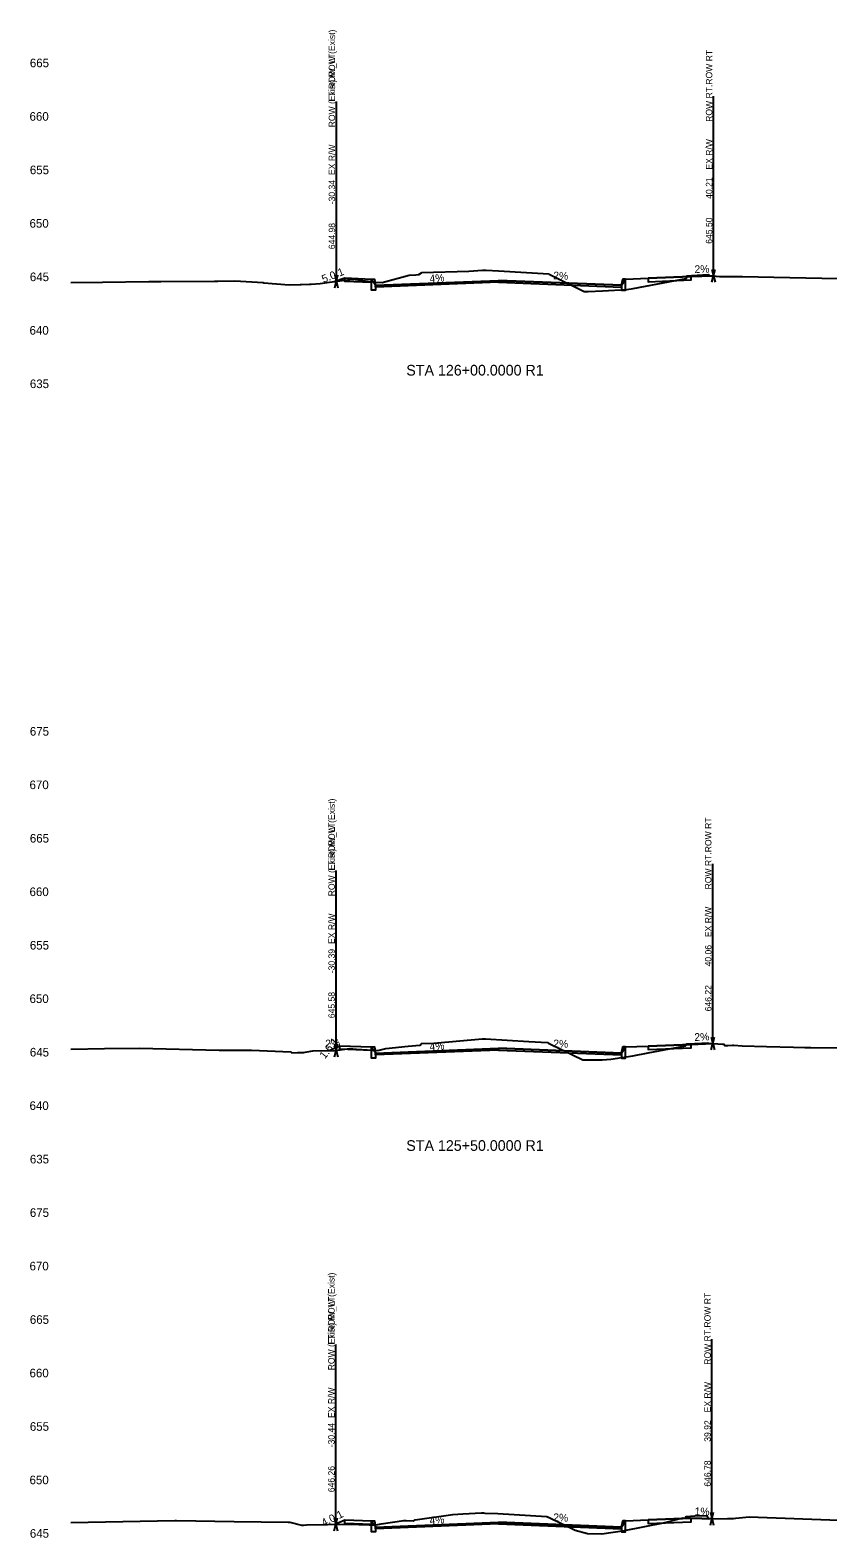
# Model space of a CAD drawing. Extents: x 2 to 741, y 16 to 2207.
# Drawn here: x 2.4 to 151.6, y 1390 to 1671.9 of the extents above; entities that cross this region are included whole.
import ezdxf

# ---------------------------------------------------------------- set-up
doc = ezdxf.new("R2010")
doc.units = 0
for name, color, linetype in [('Draft_XS_Feature_Name', 7, 'Continuous'), ('Draft_XS_Label', 7, 'Continuous'), ('Draft_XS_Point_Label_Indicator', 7, 'Continuous'), ('Draft_XS_Terminator', 7, 'Continuous'), ('Draft_XS_Text', 7, 'Continuous'), ('E_ROW', 7, 'Continuous'), ('E_Terrain_Exterior', 7, 'Continuous'), ('E_Terrain_Points_Low', 7, 'Continuous'), ('Grade_Veg_Grass', 7, 'Continuous'), ('P_XS_Sections', 7, 'Continuous'), ('Road_Curb', 7, 'Continuous'), ('Road_Pave_Asphalt', 7, 'Continuous'), ('Road_Sidewalk', 7, 'Continuous'), ('Terrain_Design', 7, 'Continuous')]:
    doc.layers.add(name, color=color, linetype=linetype)

msp = doc.modelspace()

# ---------------------------------------------------------------- linework, layer by layer
at = {"layer": 'Draft_XS_Terminator'}
for p, q in [((59.66, 1624.97), (59.66, 1646.97)), ((59.66, 1624.97), (59.66, 1646.97)), ((130.21, 1625.99), (130.21, 1647.99)), ((59.61, 1481.16), (59.61, 1503.16)), ((59.61, 1481.16), (59.61, 1503.16)), ((130.06, 1482.44), (130.06, 1504.44)), ((129.92, 1393.55), (129.92, 1415.55)), ((59.56, 1392.51), (59.56, 1414.51)), ((59.56, 1392.51), (59.56, 1414.51))]:
    msp.add_line(p, q, dxfattribs=at)
at = {"layer": 'E_ROW'}
for p, q in [((59.66, 1624.97), (59.66, 1658.57)), ((59.66, 1624.97), (59.66, 1658.57)), ((130.21, 1625.99), (130.21, 1659.59)), ((129.91, 1624.79), (130.51, 1627.19)), ((129.91, 1627.19), (130.51, 1624.79)), ((59.36, 1623.77), (59.96, 1626.17)), ((59.36, 1626.17), (59.96, 1623.77)), ((59.36, 1623.77), (59.96, 1626.17)), ((59.36, 1626.17), (59.96, 1623.77)), ((59.61, 1481.16), (59.61, 1514.76)), ((59.61, 1481.16), (59.61, 1514.76)), ((130.06, 1482.44), (130.06, 1516.04)), ((129.76, 1481.24), (130.36, 1483.64)), ((129.76, 1483.64), (130.36, 1481.24)), ((59.31, 1479.96), (59.91, 1482.36)), ((59.31, 1482.36), (59.91, 1479.96)), ((59.31, 1479.96), (59.91, 1482.36)), ((59.31, 1482.36), (59.91, 1479.96)), ((129.92, 1393.55), (129.92, 1427.15)), ((59.56, 1392.51), (59.56, 1426.11)), ((59.56, 1392.51), (59.56, 1426.11)), ((59.26, 1391.31), (59.86, 1393.71)), ((59.26, 1393.71), (59.86, 1391.31)), ((59.26, 1391.31), (59.86, 1393.71)), ((59.26, 1393.71), (59.86, 1391.31)), ((129.62, 1392.35), (130.22, 1394.75)), ((129.62, 1394.75), (130.22, 1392.35))]:
    msp.add_line(p, q, dxfattribs=at)
at = {"layer": 'E_Terrain_Exterior'}
for points in [[(10, 1624.72), (15.93, 1624.83), (24.58, 1624.94), (26.83, 1624.95), (36.85, 1624.99), (37.49, 1625), (40.69, 1625.04), (45.95, 1624.72), (46.06, 1624.71), (50.84, 1624.32), (52.86, 1624.39), (52.94, 1624.39), (52.99, 1624.39), (53.09, 1624.4), (54.61, 1624.45), (54.94, 1624.46), (56.62, 1624.55), (58.38, 1624.78), (62.66, 1625.4), (67.06, 1624.84), (68.2, 1624.77), (73.3, 1626.09), (74.49, 1626.2), (75.11, 1626.26), (75.57, 1626.56), (75.63, 1626.63), (84.44, 1626.84), (87.02, 1627.08), (87.14, 1627.07), (87.7, 1627.06), (90.01, 1626.92), (99.38, 1626.34), (99.44, 1626.3), (100.72, 1625.7), (106.01, 1623.04), (106.75, 1623.04), (109.47, 1623.16), (113.97, 1623.45), (115.15, 1623.62), (123.08, 1625.13), (125.08, 1625.52), (125.13, 1625.57), (125.29, 1625.99), (126.1, 1626.03), (129.27, 1626.24), (129.48, 1626.05), (131.35, 1625.9), (131.46, 1625.9), (131.87, 1625.89), (132.04, 1625.89), (132.23, 1625.88), (133.08, 1625.87), (134.11, 1625.85), (135.61, 1625.88), (141.49, 1625.77), (153.47, 1625.52)], [(10, 1481.37), (16.27, 1481.48), (22.83, 1481.53), (37.76, 1481.21), (43.76, 1481.16), (51.15, 1480.85), (51.3, 1480.69), (52.41, 1480.73), (52.48, 1480.73), (52.55, 1480.73), (53.29, 1480.76), (53.51, 1480.77), (53.56, 1480.77), (53.82, 1480.78), (55.26, 1481.04), (59.48, 1481.14), (62.09, 1481.52), (63.41, 1481.35), (67.4, 1481.11), (68.93, 1481.5), (73.11, 1481.91), (75.28, 1482.13), (75.4, 1482.2), (75.61, 1482.44), (77.88, 1482.49), (86.92, 1483.33), (87.35, 1483.31), (87.57, 1483.31), (95.65, 1482.81), (99.12, 1482.6), (99.34, 1482.48), (103.85, 1480.33), (105.78, 1479.36), (108.39, 1479.35), (109.38, 1479.39), (111.02, 1479.5), (115.1, 1480.11), (118, 1480.66), (124.96, 1482.02), (125.13, 1482.19), (125.19, 1482.34), (128, 1482.5), (129.16, 1482.58), (129.23, 1482.51), (131.94, 1482.28), (132.13, 1482.32), (132.24, 1482.07), (132.45, 1482.08), (132.62, 1482.08), (132.81, 1482.08), (132.87, 1482.08), (133.74, 1482.09), (134.01, 1482.1), (135.58, 1482.02), (140.12, 1481.86), (145.17, 1481.76), (147.28, 1481.71), (148.4, 1481.69), (166.65, 1481.64)], [(10, 1392.85), (29.45, 1393.2), (29.74, 1393.21), (40.54, 1393.06), (50.67, 1392.92), (50.85, 1392.92), (50.85, 1392.91), (50.93, 1392.89), (53.14, 1392.34), (53.5, 1392.36), (54.06, 1392.39), (61.9, 1392.56), (65.79, 1392.38), (67.07, 1392.43), (68.06, 1392.57), (72.29, 1393.2), (72.74, 1393.23), (74.11, 1393.14), (74.14, 1393.16), (74.42, 1393.33), (81.43, 1394.34), (83.29, 1394.47), (86.82, 1394.64), (87.02, 1394.64), (87.15, 1394.63), (87.45, 1394.62), (89.83, 1394.52), (99.01, 1393.96), (99.25, 1393.82), (99.32, 1393.82), (104.35, 1391.43), (106.63, 1390.76), (109.34, 1390.75), (113.58, 1391.38), (120.82, 1392.79), (124.53, 1393.71), (124.9, 1393.66), (125.05, 1393.8), (125.11, 1393.99), (127.54, 1394.14), (128.97, 1394.1), (129.18, 1393.6), (129.22, 1393.55), (132.82, 1393.59), (132.88, 1393.59), (132.96, 1393.59), (133.38, 1393.59), (133.91, 1393.59), (133.94, 1393.59), (134.38, 1393.68), (136.86, 1393.88), (155.31, 1393.21)]]:
    msp.add_lwpolyline(points, dxfattribs=at)
at = {"layer": 'Grade_Veg_Grass'}
for points in [[(59.25, 1624.91), (59.25, 1624.91), (61.25, 1625.6)], [(113.75, 1625.4), (118, 1625.57)], [(130, 1626.01), (126, 1625.89), (126, 1625.89)], [(58.28, 1481.11), (58.28, 1481.11), (60.28, 1482.02)], [(113.75, 1481.78), (118, 1481.95)], [(130, 1482.45), (126, 1482.27), (126, 1482.27)], [(59.25, 1392.5), (59.25, 1392.5), (61.25, 1393.36)], [(113.75, 1393.16), (118, 1393.33)], [(130, 1393.55), (130, 1393.55), (126, 1393.65)]]:
    msp.add_lwpolyline(points, dxfattribs=at)
at = {"layer": 'Road_Curb'}
for points in [[(67, 1624.23), (67, 1623.32), (66.25, 1623.32), (66.25, 1625.4), (66.77, 1625.4), (67, 1624.23)], [(113, 1624.23), (113, 1623.32), (113.75, 1623.32), (113.75, 1625.4), (113.23, 1625.4), (113, 1624.23)], [(67, 1480.61), (67, 1479.7), (66.25, 1479.7), (66.25, 1481.78), (66.77, 1481.78), (67, 1480.61)], [(113, 1480.61), (113, 1479.7), (113.75, 1479.7), (113.75, 1481.78), (113.23, 1481.78), (113, 1480.61)], [(67, 1391.99), (67, 1391.08), (66.25, 1391.08), (66.25, 1393.16), (66.77, 1393.16), (67, 1391.99)], [(113, 1391.99), (113, 1391.08), (113.75, 1391.08), (113.75, 1393.16), (113.23, 1393.16), (113, 1391.99)]]:
    msp.add_lwpolyline(points, dxfattribs=at)
at = {"layer": 'Road_Pave_Asphalt'}
for points in [[(90, 1625.15), (90, 1624.82), (67, 1623.9), (67, 1624.23), (90, 1625.15)], [(90, 1625.15), (90, 1624.82), (113, 1623.9), (113, 1624.23), (90, 1625.15)], [(90, 1481.53), (90, 1481.2), (67, 1480.28), (67, 1480.61), (90, 1481.53)], [(90, 1481.53), (90, 1481.2), (113, 1480.28), (113, 1480.61), (90, 1481.53)], [(90, 1392.91), (90, 1392.58), (67, 1391.66), (67, 1391.99), (90, 1392.91)], [(90, 1392.91), (90, 1392.58), (113, 1391.66), (113, 1391.99), (90, 1392.91)]]:
    msp.add_lwpolyline(points, dxfattribs=at)
at = {"layer": 'Road_Sidewalk'}
for points in [[(66.25, 1625.4), (66.25, 1624.73), (61.25, 1624.93), (61.25, 1625.6), (66.25, 1625.4)], [(118, 1625.57), (118, 1624.9), (126, 1625.22), (126, 1625.89), (118, 1625.57)], [(66.25, 1481.78), (66.25, 1481.11), (60.28, 1481.35), (60.28, 1482.02), (66.25, 1481.78)], [(118, 1481.95), (118, 1481.28), (126, 1481.6), (126, 1482.27), (118, 1481.95)], [(66.25, 1393.16), (66.25, 1392.49), (61.25, 1392.69), (61.25, 1393.36), (66.25, 1393.16)], [(118, 1393.33), (118, 1392.66), (126, 1392.98), (126, 1393.65), (118, 1393.33)]]:
    msp.add_lwpolyline(points, dxfattribs=at)
at = {"layer": 'Terrain_Design'}
for points in [[(59.25, 1624.91), (59.25, 1624.91), (61.25, 1625.6), (66.25, 1625.4), (66.77, 1625.4), (67, 1624.23), (90, 1625.15), (113, 1624.23), (113.23, 1625.4), (113.75, 1625.4), (118, 1625.57), (126, 1625.89), (130, 1626.01)], [(59.25, 1624.91), (59.25, 1624.91), (61.25, 1625.6), (66.25, 1625.4), (66.77, 1624.59), (67, 1624.23), (90, 1625.15), (113, 1624.23), (113.23, 1624.59), (113.75, 1625.4), (118, 1625.57), (126, 1625.89), (130, 1626.01)], [(58.28, 1481.11), (58.28, 1481.11), (60.28, 1482.02), (66.25, 1481.78), (66.77, 1481.78), (67, 1480.61), (90, 1481.53), (113, 1480.61), (113.23, 1481.78), (113.75, 1481.78), (118, 1481.95), (126, 1482.27), (130, 1482.45)], [(58.28, 1481.11), (58.28, 1481.11), (60.28, 1482.02), (66.25, 1481.78), (66.77, 1480.97), (67, 1480.61), (90, 1481.53), (113, 1480.61), (113.23, 1480.97), (113.75, 1481.78), (118, 1481.95), (126, 1482.27), (130, 1482.45)], [(59.25, 1392.5), (61.25, 1393.36), (66.25, 1393.16), (66.77, 1393.16), (67, 1391.99), (90, 1392.91), (113, 1391.99), (113.23, 1393.16), (113.75, 1393.16), (118, 1393.33), (126, 1393.65), (130, 1393.55)], [(59.25, 1392.5), (61.25, 1393.36), (66.25, 1393.16), (66.77, 1392.35), (67, 1391.99), (90, 1392.91), (113, 1391.99), (113.23, 1392.35), (113.75, 1393.16), (118, 1393.33), (126, 1393.65), (130, 1393.55)]]:
    msp.add_lwpolyline(points, dxfattribs=at)

# ---------------------------------------------------------------- texts
at = {"layer": 'Draft_XS_Feature_Name'}
for s, p in [('ROW (Exist).ROW (Exist)', (59.42, 1653.77)), ('ROW_LT.ROW_LT', (59.42, 1653.77)), ('ROW RT.ROW RT', (129.97, 1654.79)), ('ROW (Exist).ROW (Exist)', (59.37, 1509.96)), ('ROW_LT.ROW_LT', (59.37, 1509.96)), ('ROW RT.ROW RT', (129.82, 1511.24)), ('ROW (Exist).ROW (Exist)', (59.32, 1421.31)), ('ROW RT.ROW RT', (129.68, 1422.35)), ('ROW_LT.ROW_LT', (59.32, 1421.31))]:
    msp.add_text(s, height=1.2, rotation=90, dxfattribs=at).set_placement(p)
at = {"layer": 'Draft_XS_Label'}
for s, p in [('-30.34', (59.42, 1639.37)), ('-30.34', (59.42, 1639.37)), ('40.21', (129.97, 1640.39)), ('644.98', (59.42, 1630.97)), ('644.98', (59.42, 1630.97)), ('645.50', (129.97, 1631.99)), ('40.06', (129.82, 1496.84)), ('-30.39', (59.37, 1495.56)), ('-30.39', (59.37, 1495.56)), ('645.58', (59.37, 1487.16)), ('645.58', (59.37, 1487.16)), ('646.22', (129.82, 1488.44)), ('-30.44', (59.32, 1406.91)), ('-30.44', (59.32, 1406.91)), ('39.92', (129.68, 1407.95)), ('646.78', (129.68, 1399.55)), ('646.26', (59.32, 1398.51)), ('646.26', (59.32, 1398.51))]:
    msp.add_text(s, height=1.2, rotation=90, dxfattribs=at).set_placement(p)
at = {"layer": 'Draft_XS_Point_Label_Indicator'}
for p in [(59.24, 1624.89), (61.24, 1625.59), (66.24, 1625.39), (66.76, 1625.39), (66.99, 1624.22), (112.99, 1624.22), (113.22, 1625.39), (113.74, 1625.39), (117.99, 1625.56), (125.99, 1625.88), (129.99, 1626), (66.99, 1623.3), (112.99, 1623.3), (58.27, 1481.1), (60.27, 1482.01), (66.24, 1481.77), (66.76, 1481.77), (66.99, 1480.6), (112.99, 1480.6), (113.22, 1481.77), (113.74, 1481.77), (117.99, 1481.94), (125.99, 1482.26), (129.99, 1482.43), (66.99, 1479.68), (112.99, 1479.68), (61.24, 1393.35), (66.24, 1393.15), (66.76, 1393.15), (113.22, 1393.15), (113.74, 1393.15), (117.99, 1393.32), (125.99, 1393.64), (129.99, 1393.54), (59.24, 1392.49), (66.99, 1391.98), (66.99, 1391.06), (112.99, 1391.98), (112.99, 1391.06)]:
    msp.add_text('X', height=0.024, dxfattribs=at).set_placement(p)
at = {"layer": 'Draft_XS_Text'}
for s, height, p in [('665', 1.608, (2.32, 1665)), ('660', 1.608, (2.26, 1655)), ('655', 1.608, (2.32, 1645)), ('650', 1.608, (2.26, 1635)), ('645', 1.608, (2.32, 1625)), ('640', 1.608, (2.26, 1615)), ('STA 126+00.0000 R1', 1.992, (72.74, 1607.35)), ('635', 1.608, (2.32, 1605)), ('675', 1.608, (2.32, 1540)), ('670', 1.608, (2.26, 1530)), ('665', 1.608, (2.32, 1520)), ('660', 1.608, (2.26, 1510)), ('655', 1.608, (2.32, 1500)), ('650', 1.608, (2.26, 1490)), ('645', 1.608, (2.32, 1480)), ('640', 1.608, (2.26, 1470)), ('STA 125+50.0000 R1', 1.992, (72.74, 1462.35)), ('635', 1.608, (2.32, 1460)), ('675', 1.608, (2.32, 1450)), ('670', 1.608, (2.26, 1440)), ('665', 1.608, (2.32, 1430)), ('660', 1.608, (2.26, 1420)), ('655', 1.608, (2.32, 1410)), ('650', 1.608, (2.26, 1400)), ('645', 1.608, (2.32, 1390))]:
    msp.add_text(s, height=height, dxfattribs=at).set_placement(p)
for s, rotation, p in [('5.0:1', 21.7584, (57.26, 1624.65)), ('2%', 1.7234, (126.67, 1626.51)), ('4%', 4.5657, (77.14, 1624.73)), ('2%', 357.7094, (100.21, 1625.35)), ('1.6:1', 52.2179, (57.51, 1479.43)), ('2%', 1.9829, (57.61, 1481.69)), ('2%', 357.7094, (100.21, 1481.73)), ('2%', 2.5153, (126.66, 1482.9)), ('4%', 4.5657, (77.14, 1481.11)), ('4.0:1', 26.6512, (57.28, 1392.04)), ('4%', 4.5657, (77.14, 1392.49)), ('2%', 357.7094, (100.21, 1393.11)), ('1%', 358.5987, (126.66, 1394.23))]:
    msp.add_text(s, height=1.44, rotation=rotation, dxfattribs=at).set_placement(p)
at = {"layer": 'E_ROW'}
for p in [(59.42, 1644.85), (59.42, 1644.85), (129.97, 1645.87), (59.37, 1501.04), (59.37, 1501.04), (129.82, 1502.32), (129.68, 1413.44), (59.32, 1412.39), (59.32, 1412.39)]:
    msp.add_text('EX R/W', height=1.2, rotation=90, dxfattribs=at).set_placement(p)
at = {"layer": 'E_Terrain_Points_Low'}
for p in [(89.99, 1625.14), (89.99, 1481.52), (89.99, 1392.9)]:
    msp.add_text('X', height=0.024, dxfattribs=at).set_placement(p)
at = {"layer": 'P_XS_Sections'}
for p in [(10, 1605), (10, 1460)]:
    msp.add_text('-', height=0.0001, dxfattribs=at).set_placement(p)

doc.saveas('drawing.dxf')
